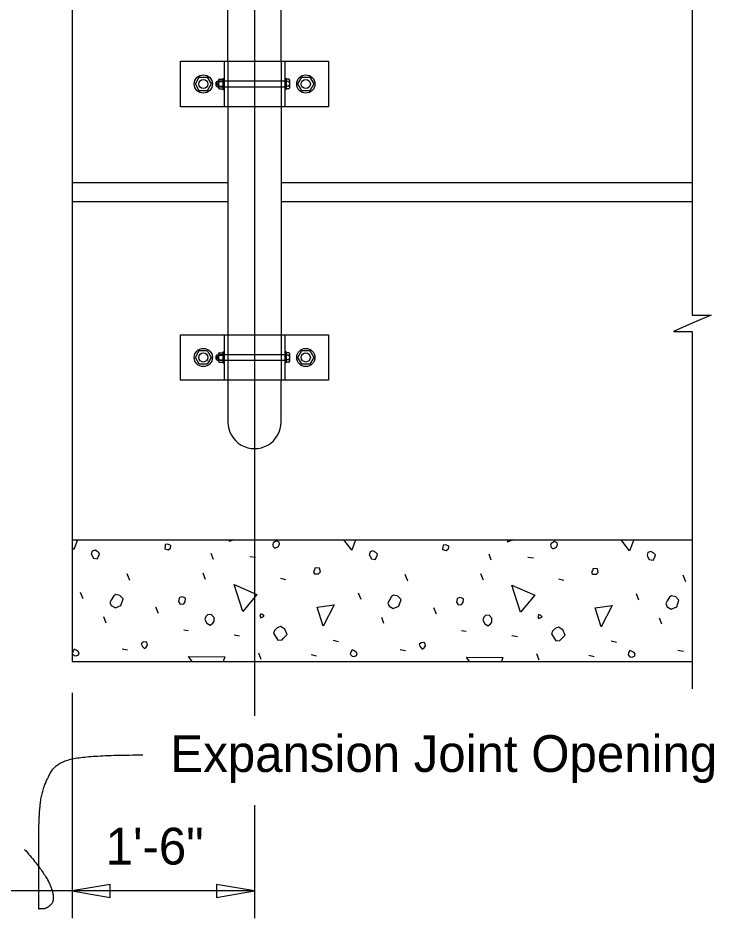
# Model space of a CAD drawing. Extents: x 0 to 41.2, y 0 to 26.
# Drawn here: x 27.279 to 31.095, y 12.395 to 17.331 of the extents above; entities that cross this region are included whole.
import ezdxf

# ---------------------------------------------------------------- set-up
doc = ezdxf.new("R2010")
doc.units = 0
for name, color, linetype in [('CL_Major', 7, 'Continuous'), ('Dimension', 7, 'Continuous'), ('Miscellaneous', 7, 'Continuous'), ('SteelMisc', 7, 'Continuous'), ('SteelMisc_h', 7, 'Continuous'), ('SupstrConc', 7, 'Continuous'), ('TextStructures', 7, 'Continuous')]:
    doc.layers.add(name, color=color, linetype=linetype)

msp = doc.modelspace()

# ---------------------------------------------------------------- linework, layer by layer
at = {"layer": 'CL_Major'}
for p, q in [((28.5763, 25.6784), (28.5763, 13.5039)), ((28.5763, 13.0148), (28.5763, 12.3953))]:
    msp.add_line(p, q, dxfattribs=at)
at = {"layer": 'Dimension'}
for p, q in [((27.5763, 13.6294), (27.5763, 12.3953)), ((28.5763, 12.5434), (26.2429, 12.5434))]:
    msp.add_line(p, q, dxfattribs=at)
for points in [[(30.9762, 20.1983), (30.9762, 19.1806), (31.0795, 19.1806), (30.9762, 19.1356), (30.8729, 19.0906), (30.9762, 19.0906), (30.9762, 17.1361)], [(30.9761, 17.1361), (30.9761, 15.7022), (31.0795, 15.7022), (30.9761, 15.6572), (30.8728, 15.6122), (30.9761, 15.6122), (30.9761, 13.653)]]:
    msp.add_lwpolyline(points, dxfattribs=at)
for points in [[(27.5762, 12.5434), (27.7845, 12.5081), (27.7845, 12.5787)], [(28.5762, 12.5434), (28.368, 12.5787), (28.368, 12.5081)]]:
    msp.add_lwpolyline(points, close=True, dxfattribs=at)
msp.add_open_spline([(27.3159, 12.7718), (27.434, 12.6355), (27.4854, 12.4962), (27.437, 12.4448), (27.3939, 12.4448), (27.3939, 12.4448), (27.3939, 12.6961), (27.3939, 12.9989), (27.4249, 13.1352), (27.4975, 13.2594), (27.7306, 13.2896), (27.9637, 13.2896)], degree=2, dxfattribs=at)
at = {"layer": 'Miscellaneous'}
for p, q in [((28.3687, 16.9625), (28.3687, 16.9746)), ((28.3744, 16.9625), (28.3744, 16.9746)), ((28.3687, 15.4625), (28.3687, 15.4746)), ((28.3744, 15.4625), (28.3744, 15.4746)), ((29.525, 14.4695), (29.5261, 14.4692)), ((28.3505, 14.3614), (28.3382, 14.395)), ((28.5503, 14.3773), (28.5821, 14.3738)), ((29.8743, 14.3579), (29.862, 14.3915)), ((30.0741, 14.3738), (30.1059, 14.3702)), ((27.8927, 14.2465), (27.8785, 14.2819)), ((28.3081, 14.2518), (28.294, 14.2872)), ((29.4165, 14.243), (29.4024, 14.2783)), ((29.8319, 14.2483), (29.8178, 14.2836)), ((30.9403, 14.2394), (30.9262, 14.2748)), ((28.7182, 14.2589), (28.7465, 14.2518)), ((30.242, 14.2553), (30.2703, 14.2483)), ((27.6364, 14.1457), (27.6222, 14.1811)), ((29.1602, 14.1422), (29.146, 14.1776)), ((30.684, 14.1387), (30.6698, 14.174)), ((28.05, 14.0644), (28.0359, 14.0998)), ((29.5738, 14.0609), (29.5597, 14.0962)), ((27.7619, 14.0131), (27.7495, 14.0467)), ((29.2857, 14.0096), (29.2733, 14.0432)), ((30.8095, 14.0061), (30.7971, 14.0397)), ((28.1879, 13.976), (28.2126, 13.9725)), ((29.7117, 13.9725), (29.7365, 13.969)), ((28.4637, 13.9477), (28.4937, 13.9424)), ((29.0081, 13.9195), (29.0364, 13.9124)), ((29.9875, 13.9442), (30.0175, 13.9389)), ((27.8503, 13.8717), (27.8803, 13.8664)), ((30.532, 13.9159), (30.5602, 13.9089)), ((28.6122, 13.8134), (28.5998, 13.847)), ((28.8862, 13.8399), (28.9145, 13.8328)), ((29.3741, 13.8682), (29.4041, 13.8629)), ((30.136, 13.8099), (30.1236, 13.8434)), ((30.41, 13.8364), (30.4383, 13.8293)), ((30.8979, 13.8647), (30.9279, 13.8594))]:
    msp.add_line(p, q, dxfattribs=at)
for points in [[(27.605, 14.4695), (27.5851, 14.4162)], [(28.4389, 14.4604), (28.4417, 14.4695)], [(28.4591, 14.4695), (28.4389, 14.4604)], [(28.6864, 14.425), (28.6935, 14.425), (28.7076, 14.4321), (28.7129, 14.448), (28.7112, 14.4569), (28.697, 14.4639), (28.6793, 14.4533), (28.6758, 14.4427), (28.6793, 14.4321), (28.6864, 14.425)], [(29.1089, 14.4127), (29.0657, 14.4695)], [(29.1301, 14.4695), (29.1089, 14.4127)], [(29.9627, 14.4569), (29.9666, 14.4695)], [(29.9908, 14.4695), (29.9627, 14.4569)], [(30.6327, 14.4091), (30.5869, 14.4695)], [(30.6553, 14.4695), (30.6327, 14.4091)], [(27.5851, 14.4162), (27.5763, 14.4278)], [(27.6841, 14.3844), (27.6929, 14.3685), (27.7141, 14.3649), (27.723, 14.3808), (27.7265, 14.395), (27.7177, 14.4038), (27.7018, 14.4127), (27.6859, 14.4074), (27.6805, 14.3915), (27.6841, 14.3844)], [(28.0836, 14.4197), (28.103, 14.4144), (28.1154, 14.4233), (28.1172, 14.4356), (28.1137, 14.4392), (28.0995, 14.4463), (28.0871, 14.4445), (28.0854, 14.4321), (28.0836, 14.4197)], [(29.6074, 14.4162), (29.6269, 14.4109), (29.6392, 14.4197), (29.641, 14.4321), (29.6375, 14.4356), (29.6233, 14.4427), (29.611, 14.4409), (29.6092, 14.4286), (29.6074, 14.4162)], [(30.2102, 14.4215), (30.2173, 14.4215), (30.2314, 14.4286), (30.2367, 14.4445), (30.235, 14.4533), (30.2208, 14.4604), (30.2032, 14.4498), (30.1996, 14.4392), (30.2032, 14.4286), (30.2102, 14.4215)], [(29.2079, 14.3808), (29.2167, 14.3649), (29.238, 14.3614), (29.2468, 14.3773), (29.2503, 14.3915), (29.2415, 14.4003), (29.2256, 14.4091), (29.2097, 14.4038), (29.2044, 14.3879), (29.2079, 14.3808)], [(30.7317, 14.3773), (30.7406, 14.3614), (30.7618, 14.3579), (30.7706, 14.3738), (30.7741, 14.3879), (30.7653, 14.3968), (30.7494, 14.4056), (30.7335, 14.4003), (30.7282, 14.3844), (30.7317, 14.3773)], [(28.9056, 14.2836), (28.9268, 14.2836), (28.9374, 14.2942), (28.9321, 14.3137), (28.9091, 14.3154), (28.9056, 14.3048), (28.9003, 14.296), (28.9056, 14.2836), (28.9021, 14.2872)], [(30.4294, 14.2801), (30.4506, 14.2801), (30.4612, 14.2907), (30.4559, 14.3101), (30.433, 14.3119), (30.4294, 14.3013), (30.4241, 14.2925), (30.4294, 14.2801), (30.4259, 14.2836)], [(28.5114, 14.0768), (28.4637, 14.2235), (28.5892, 14.1687), (28.5114, 14.0768)], [(30.0352, 14.0733), (29.9875, 14.22), (30.113, 14.1652), (30.0352, 14.0733)], [(27.7902, 14.1086), (27.8131, 14.0962), (27.8432, 14.1086), (27.8556, 14.1457), (27.8379, 14.1634), (27.8149, 14.1687), (27.8043, 14.1616), (27.7919, 14.1422), (27.7831, 14.1263), (27.7902, 14.1086)], [(28.1596, 14.1316), (28.1685, 14.1157), (28.1879, 14.1174), (28.1967, 14.1298), (28.1985, 14.1493), (28.1861, 14.1546), (28.1773, 14.1563), (28.1667, 14.1528), (28.1631, 14.1493), (28.1596, 14.1316)], [(29.314, 14.1051), (29.3369, 14.0927), (29.367, 14.1051), (29.3794, 14.1422), (29.3617, 14.1599), (29.3387, 14.1652), (29.3281, 14.1581), (29.3157, 14.1387), (29.3069, 14.1228), (29.314, 14.1051)], [(29.6834, 14.1281), (29.6923, 14.1121), (29.7117, 14.1139), (29.7206, 14.1263), (29.7223, 14.1457), (29.7099, 14.151), (29.7011, 14.1528), (29.6905, 14.1493), (29.687, 14.1457), (29.6834, 14.1281)], [(30.8378, 14.1015), (30.8608, 14.0892), (30.8908, 14.1015), (30.9032, 14.1387), (30.8855, 14.1563), (30.8625, 14.1616), (30.8519, 14.1546), (30.8395, 14.1351), (30.8307, 14.1192), (30.8378, 14.1015)], [(28.9533, 13.9955), (28.9198, 14.0998), (29.0134, 14.1121), (28.9533, 13.9955)], [(30.4772, 13.9919), (30.4436, 14.0962), (30.5373, 14.1086), (30.4772, 13.9919)], [(28.3046, 14.0326), (28.3152, 14.0114), (28.3329, 14.0008), (28.347, 14.0114), (28.3541, 14.022), (28.3541, 14.0432), (28.3382, 14.0591), (28.3187, 14.0573), (28.3099, 14.0485), (28.3046, 14.0326)], [(28.6104, 14.0414), (28.6298, 14.0503), (28.6228, 14.0573), (28.6104, 14.0626), (28.6051, 14.0503), (28.6104, 14.0414)], [(29.8284, 14.0291), (29.839, 14.0078), (29.8567, 13.9972), (29.8708, 14.0078), (29.8779, 14.0185), (29.8779, 14.0397), (29.862, 14.0556), (29.8425, 14.0538), (29.8337, 14.045), (29.8284, 14.0291)], [(30.1342, 14.0379), (30.1537, 14.0467), (30.1466, 14.0538), (30.1342, 14.0591), (30.1289, 14.0467), (30.1342, 14.0379)], [(28.6811, 13.9566), (28.7041, 13.9195), (28.7271, 13.9212), (28.7359, 13.9301), (28.7554, 13.9495), (28.743, 13.9796), (28.7182, 13.9937), (28.7006, 13.9866), (28.6864, 13.9725), (28.6811, 13.9566)], [(30.2049, 13.953), (30.2279, 13.9159), (30.2509, 13.9177), (30.2597, 13.9265), (30.2792, 13.946), (30.2668, 13.976), (30.242, 13.9902), (30.2244, 13.9831), (30.2102, 13.969), (30.2049, 13.953)], [(27.5869, 13.8346), (27.5992, 13.8328), (27.6116, 13.8381), (27.6151, 13.8487), (27.6098, 13.8576), (27.5992, 13.8647), (27.5869, 13.87), (27.5798, 13.8558), (27.5763, 13.8452), (27.5869, 13.8346)], [(27.9616, 13.8841), (27.9722, 13.8735), (27.9828, 13.8806), (27.9899, 13.8912), (27.9864, 13.9089), (27.9775, 13.9106), (27.9652, 13.9089), (27.9546, 13.8982), (27.9616, 13.8841)], [(29.4854, 13.8806), (29.496, 13.87), (29.5067, 13.877), (29.5137, 13.8876), (29.5102, 13.9053), (29.5013, 13.9071), (29.489, 13.9053), (29.4784, 13.8947), (29.4854, 13.8806)], [(28.2346, 13.8028), (28.2144, 13.8293), (28.4142, 13.8275), (28.4049, 13.8028)], [(29.1107, 13.8311), (29.123, 13.8293), (29.1354, 13.8346), (29.139, 13.8452), (29.1337, 13.8541), (29.123, 13.8611), (29.1107, 13.8664), (29.1036, 13.8523), (29.1001, 13.8417), (29.1107, 13.8311)], [(29.7557, 13.8028), (29.7382, 13.8258), (29.938, 13.824), (29.9301, 13.8028)], [(30.6345, 13.8275), (30.6469, 13.8258), (30.6592, 13.8311), (30.6628, 13.8417), (30.6575, 13.8505), (30.6469, 13.8576), (30.6345, 13.8629), (30.6274, 13.8487), (30.6239, 13.8381), (30.6345, 13.8275)]]:
    msp.add_lwpolyline(points, dxfattribs=at)
at = {"layer": 'SteelMisc'}
for p, q in [((28.4305, 17.0944), (28.4305, 17.6079)), ((28.7221, 17.0944), (28.7221, 17.6079)), ((28.1703, 17.0944), (28.9823, 17.0944)), ((28.1703, 16.8444), (28.1703, 17.0944)), ((28.4096, 17.0944), (28.4096, 16.8444)), ((28.743, 17.0944), (28.743, 16.8444)), ((28.9823, 17.0944), (28.9823, 16.8444)), ((28.3659, 16.9774), (28.3715, 16.984)), ((28.3715, 16.984), (28.3781, 16.984)), ((28.3715, 16.9541), (28.3715, 16.984)), ((28.3781, 16.9873), (28.3781, 16.9516)), ((28.3828, 16.9824), (28.4031, 16.9824)), ((28.383, 16.9954), (28.4031, 16.9954)), ((28.4031, 16.9997), (28.4031, 16.9391)), ((28.4031, 16.9997), (28.4096, 16.9997)), ((28.4031, 16.9954), (28.4031, 16.9435)), ((28.7492, 16.9997), (28.7432, 16.9997)), ((28.7492, 16.9997), (28.7492, 16.9391)), ((28.7639, 16.9954), (28.7492, 16.9954)), ((28.7641, 16.9824), (28.7492, 16.9824)), ((28.769, 16.95), (28.769, 16.9889)), ((28.3659, 16.9597), (28.3659, 16.9774)), ((28.3659, 16.9597), (28.3715, 16.9541)), ((28.3715, 16.9541), (28.3781, 16.9541)), ((28.3828, 16.9565), (28.4031, 16.9565)), ((28.3831, 16.9435), (28.4031, 16.9435)), ((28.4031, 16.9391), (28.4096, 16.9391)), ((28.7492, 16.9391), (28.7432, 16.9391)), ((28.7641, 16.9564), (28.7492, 16.9564)), ((28.7639, 16.9434), (28.7492, 16.9434)), ((28.9823, 16.8444), (28.1703, 16.8444)), ((28.4305, 16.8444), (28.4305, 15.5944)), ((28.7221, 16.8444), (28.7221, 15.5944)), ((28.1703, 15.5944), (28.9823, 15.5944)), ((28.1703, 15.3444), (28.1703, 15.5944)), ((28.4096, 15.5944), (28.4096, 15.3444)), ((28.743, 15.5944), (28.743, 15.3444)), ((28.9823, 15.5944), (28.9823, 15.3444)), ((28.4031, 15.4997), (28.4031, 15.4391)), ((28.4031, 15.4997), (28.4096, 15.4997)), ((28.7492, 15.4997), (28.7432, 15.4997)), ((28.7492, 15.4997), (28.7492, 15.4391)), ((28.3659, 15.4774), (28.3715, 15.484)), ((28.3659, 15.4597), (28.3659, 15.4774)), ((28.3659, 15.4597), (28.3715, 15.4541)), ((28.3715, 15.484), (28.3781, 15.484)), ((28.3715, 15.4541), (28.3715, 15.484)), ((28.3715, 15.4541), (28.3781, 15.4541)), ((28.3781, 15.4873), (28.3781, 15.4516)), ((28.3828, 15.4824), (28.4031, 15.4824)), ((28.3828, 15.4565), (28.4031, 15.4565)), ((28.383, 15.4954), (28.4031, 15.4954)), ((28.4031, 15.4954), (28.4031, 15.4435)), ((28.7639, 15.4954), (28.7492, 15.4954)), ((28.7641, 15.4824), (28.7492, 15.4824)), ((28.7641, 15.4564), (28.7492, 15.4564)), ((28.769, 15.45), (28.769, 15.4889)), ((28.3831, 15.4435), (28.4031, 15.4435)), ((28.4031, 15.4391), (28.4096, 15.4391)), ((28.7492, 15.4391), (28.7432, 15.4391)), ((28.7639, 15.4434), (28.7492, 15.4434)), ((28.9823, 15.3444), (28.1703, 15.3444)), ((28.4303, 15.3444), (28.4303, 15.1153)), ((28.722, 15.1153), (28.722, 15.3444))]:
    msp.add_line(p, q, dxfattribs=at)
for points in [[(28.2736, 17.007), (28.317, 17.007), (28.3386, 16.9694), (28.317, 16.9319), (28.2736, 16.9319), (28.252, 16.9694)], [(28.8356, 17.007), (28.8789, 17.007), (28.9006, 16.9694), (28.8789, 16.9319), (28.8356, 16.9319), (28.8139, 16.9694)], [(28.2736, 15.507), (28.317, 15.507), (28.3386, 15.4694), (28.317, 15.4319), (28.2736, 15.4319), (28.252, 15.4694)], [(28.8356, 15.507), (28.8789, 15.507), (28.9006, 15.4694), (28.8789, 15.4319), (28.8356, 15.4319), (28.8139, 15.4694)]]:
    msp.add_lwpolyline(points, close=True, dxfattribs=at)
for centre, radius in [((28.2953, 16.9694), 0.05), ((28.2953, 16.9694), 0.025), ((28.8573, 16.9694), 0.05), ((28.8573, 16.9694), 0.025), ((28.2953, 15.4694), 0.05), ((28.8573, 15.4694), 0.05), ((28.2953, 15.4694), 0.025), ((28.8573, 15.4694), 0.025)]:
    msp.add_circle(centre, radius, dxfattribs=at)
for centre, radius, start, end in [((28.3846, 16.9889), 0.00674, 104.4891, 254.1889), ((28.3975, 16.9694), 0.0196, 138.628, 221.372), ((28.7622, 16.9889), 0.00673, 285.7823, 75.5404), ((28.7493, 16.9694), 0.0196, 318.628, 41.372), ((28.3846, 16.95), 0.00673, 105.7823, 255.5404), ((28.7622, 16.95), 0.00674, 284.4891, 74.1889), ((28.3846, 15.4889), 0.00674, 104.4891, 254.1889), ((28.3975, 15.4694), 0.0196, 138.628, 221.372), ((28.3846, 15.45), 0.00673, 105.7823, 255.5404), ((28.7622, 15.4889), 0.00673, 285.7823, 75.5404), ((28.7622, 15.45), 0.00674, 284.4891, 74.1889), ((28.7493, 15.4694), 0.0196, 318.628, 41.372)]:
    msp.add_arc(centre, radius, start, end, dxfattribs=at)
msp.add_ellipse((28.5763, 15.1153), major_axis=(0, 0.1458), ratio=0.999499, start_param=1.570796, end_param=4.712389, dxfattribs=at)
at = {"layer": 'SteelMisc_h'}
for p, q in [((28.4305, 17.0944), (28.4305, 16.8444)), ((28.7221, 17.0944), (28.7221, 16.8444)), ((28.743, 16.984), (28.3781, 16.984)), ((28.3781, 16.9541), (28.743, 16.9541)), ((28.4305, 15.5944), (28.4305, 15.3444)), ((28.7221, 15.5944), (28.7221, 15.3444)), ((28.743, 15.484), (28.3781, 15.484)), ((28.3781, 15.4541), (28.743, 15.4541))]:
    msp.add_line(p, q, dxfattribs=at)
at = {"layer": 'SupstrConc'}
for p, q in [((27.5763, 17.4693), (27.5763, 13.8028)), ((27.5763, 16.4295), (28.4305, 16.4295)), ((28.7221, 16.4295), (30.976, 16.4295)), ((27.5763, 16.3254), (28.4305, 16.3254)), ((28.7221, 16.3254), (30.976, 16.3254)), ((27.5763, 14.4695), (30.9761, 14.4695)), ((27.5763, 13.8028), (30.9761, 13.8028))]:
    msp.add_line(p, q, dxfattribs=at)

# ---------------------------------------------------------------- texts
at = {"layer": 'TextStructures'}
for s, p in [('Expansion Joint Opening', (28.1153, 13.1963)), ('1\'-6"', (27.7605, 12.6886))]:
    msp.add_text(s, height=0.2016, dxfattribs=at).set_placement(p)

doc.saveas('drawing.dxf')
